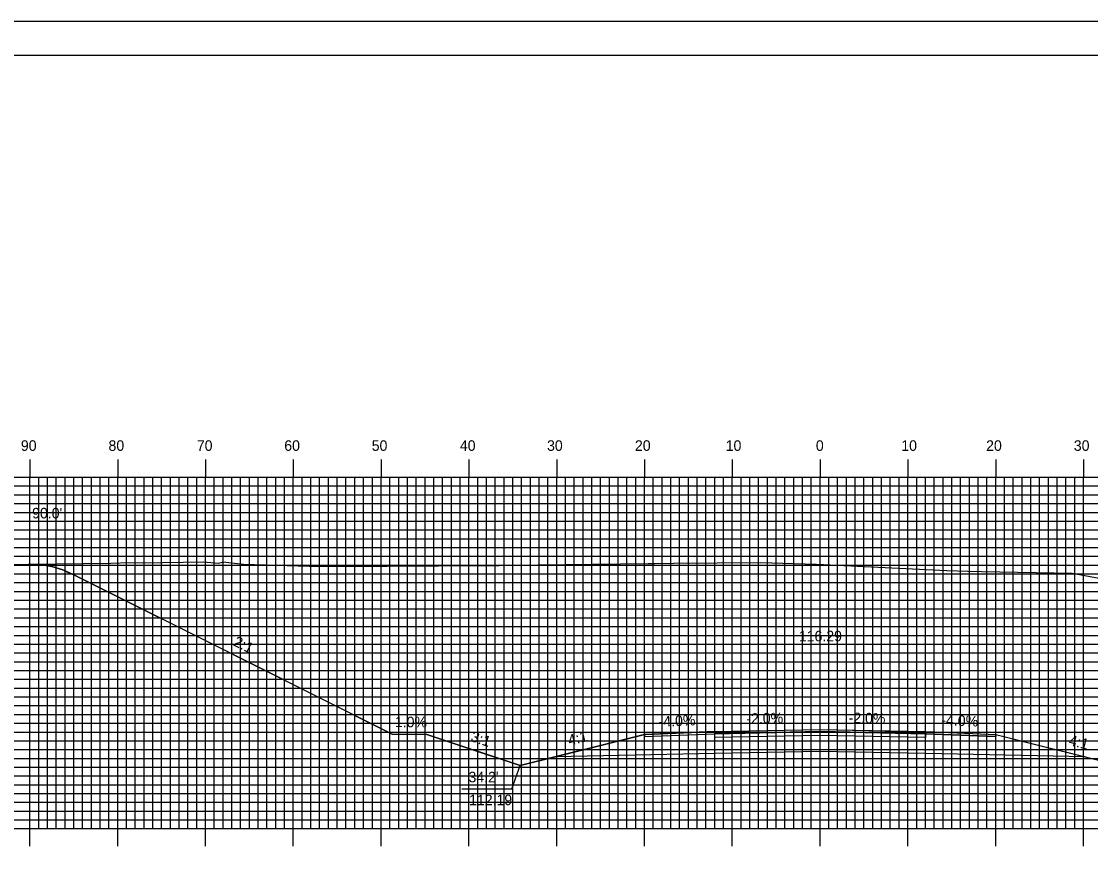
# Model space of a CAD drawing. Extents: x 1768087 to 1768430, y 442591 to 442811.
# Drawn here: x 1768162 to 1768283.8, y 442716.2 to 442810.5 of the extents above; entities that cross this region are included whole.
import ezdxf

# ---------------------------------------------------------------- set-up
doc = ezdxf.new("R2010")
doc.units = 0
for name, color, linetype in [('ANNOTATION', 7, 'Continuous'), ('BORDER', 7, 'Continuous'), ('D_Roadway_Centerline', 7, 'Continuous'), ('D_Roadway_Centerline_Text', 7, 'Continuous'), ('D_Roadway_Edge_Shoulder', 7, 'Continuous'), ('D_Roadway_Edge_TW', 7, 'Continuous'), ('D_Roadway_Pavement', 7, 'Continuous'), ('D_Roadway_SlopeLines', 7, 'Continuous'), ('D_Roadway_SubGrade', 7, 'Continuous'), ('D_Text_Standard', 7, 'Continuous'), ('H_V ANNOTATION', 7, 'Continuous'), ('MAJOR', 7, 'Continuous'), ('MINOR', 7, 'Continuous'), ('PLOT BOUNDARY', 7, 'Continuous'), ('S_Roadway_Centerline', 7, 'Continuous')]:
    doc.layers.add(name, color=color, linetype=linetype)

msp = doc.modelspace()

# ---------------------------------------------------------------- linework, layer by layer
at = {"layer": 'ANNOTATION'}
msp.add_lwpolyline([(1768212.17, 442723.21), (1768217.86, 442723.21), (1768218.79, 442725.85)], dxfattribs=at)
at = {"layer": 'BORDER'}
msp.add_lwpolyline([(1768103.36, 442596.67), (1768423.36, 442596.67), (1768423.36, 442806.67), (1768103.36, 442806.67)], close=True, dxfattribs=at)
at = {"layer": 'D_Roadway_Centerline'}
msp.add_lwpolyline([(1768162.96, 442748.79), (1768163.48, 442748.76), (1768164.21, 442748.72), (1768164.59, 442748.65), (1768165.46, 442748.5), (1768166.71, 442748.11), (1768167.18, 442747.91), (1768167.96, 442747.57), (1768187.51, 442737.79), (1768204.22, 442729.44), (1768208.16, 442729.4), (1768213.05, 442727.77), (1768218.79, 442725.85), (1768218.79, 442725.85), (1768218.79, 442725.85), (1768222.79, 442726.85), (1768232.96, 442729.4), (1768232.96, 442729.4), (1768240.96, 442729.72), (1768240.96, 442729.72), (1768252.96, 442729.96), (1768252.96, 442729.96), (1768264.06, 442729.73), (1768264.96, 442729.72), (1768272.96, 442729.4), (1768276.27, 442728.57), (1768283.14, 442726.85), (1768287.14, 442725.85)], dxfattribs=at)
at = {"layer": 'D_Roadway_Edge_Shoulder'}
for points in [[(1768240.96, 442729.72), (1768232.96, 442729.4), (1768232.96, 442729.15), (1768240.96, 442729.47)], [(1768264.96, 442729.72), (1768272.96, 442729.4), (1768272.96, 442729.15), (1768264.96, 442729.47)]]:
    msp.add_lwpolyline(points, close=True, dxfattribs=at)
at = {"layer": 'D_Roadway_Edge_TW'}
msp.add_lwpolyline([(1768240.96, 442729.47), (1768240.96, 442729.72), (1768252.96, 442729.96), (1768264.96, 442729.72), (1768264.96, 442729.47), (1768252.96, 442729.71)], close=True, dxfattribs=at)
at = {"layer": 'D_Roadway_Pavement'}
msp.add_lwpolyline([(1768240.96, 442729.05), (1768240.96, 442729.47), (1768252.96, 442729.71), (1768264.96, 442729.47), (1768264.96, 442729.05), (1768252.96, 442729.29)], close=True, dxfattribs=at)
at = {"layer": 'D_Roadway_SlopeLines'}
for points in [[(1768208.16, 442729.4), (1768204.22, 442729.44), (1768167.96, 442747.57), (1768166.71, 442748.11), (1768165.46, 442748.5), (1768164.21, 442748.72), (1768162.96, 442748.79)], [(1768218.79, 442725.85), (1768208.16, 442729.4)], [(1768232.96, 442729.4), (1768218.79, 442725.85)], [(1768272.96, 442729.4), (1768287.14, 442725.85)]]:
    msp.add_lwpolyline(points, dxfattribs=at)
at = {"layer": 'D_Roadway_SubGrade'}
msp.add_lwpolyline([(1768240.96, 442727.22), (1768222.79, 442726.85), (1768232.96, 442729.4), (1768232.96, 442729.15), (1768240.96, 442729.47), (1768252.96, 442729.71), (1768264.96, 442729.47), (1768272.96, 442729.15), (1768272.96, 442729.4), (1768283.14, 442726.85), (1768264.96, 442727.22), (1768252.96, 442727.46)], close=True, dxfattribs=at)
at = {"layer": 'MAJOR'}
for p, q in [((1768162.96, 442760.67), (1768162.96, 442758.67)), ((1768172.96, 442760.67), (1768172.96, 442758.67)), ((1768182.96, 442760.67), (1768182.96, 442758.67)), ((1768192.96, 442760.67), (1768192.96, 442758.67)), ((1768202.96, 442760.67), (1768202.96, 442758.67)), ((1768212.96, 442760.67), (1768212.96, 442758.67)), ((1768222.96, 442760.67), (1768222.96, 442758.67)), ((1768232.96, 442760.67), (1768232.96, 442758.67)), ((1768242.96, 442760.67), (1768242.96, 442758.67)), ((1768252.96, 442760.67), (1768252.96, 442758.67)), ((1768262.96, 442760.67), (1768262.96, 442758.67)), ((1768272.96, 442760.67), (1768272.96, 442758.67)), ((1768282.96, 442760.67), (1768282.96, 442758.67)), ((1768112.96, 442758.67), (1768392.96, 442758.67)), ((1768112.96, 442758.67), (1768392.96, 442758.67)), ((1768162.96, 442718.67), (1768162.96, 442758.67)), ((1768172.96, 442718.67), (1768172.96, 442758.67)), ((1768182.96, 442718.67), (1768182.96, 442758.67)), ((1768192.96, 442718.67), (1768192.96, 442758.67)), ((1768202.96, 442718.67), (1768202.96, 442758.67)), ((1768212.96, 442718.67), (1768212.96, 442758.67)), ((1768222.96, 442718.67), (1768222.96, 442758.67)), ((1768232.96, 442718.67), (1768232.96, 442758.67)), ((1768242.96, 442718.67), (1768242.96, 442758.67)), ((1768252.96, 442718.67), (1768252.96, 442758.67)), ((1768262.96, 442718.67), (1768262.96, 442758.67)), ((1768272.96, 442718.67), (1768272.96, 442758.67)), ((1768282.96, 442718.67), (1768282.96, 442758.67)), ((1768112.96, 442753.67), (1768392.96, 442753.67)), ((1768112.96, 442748.67), (1768392.96, 442748.67)), ((1768112.96, 442743.67), (1768392.96, 442743.67)), ((1768112.96, 442738.67), (1768392.96, 442738.67)), ((1768112.96, 442733.67), (1768392.96, 442733.67)), ((1768112.96, 442728.67), (1768392.96, 442728.67)), ((1768112.96, 442723.67), (1768392.96, 442723.67)), ((1768112.96, 442718.67), (1768392.96, 442718.67)), ((1768112.96, 442718.67), (1768392.96, 442718.67)), ((1768162.96, 442716.66), (1768162.96, 442718.67)), ((1768172.96, 442716.66), (1768172.96, 442718.67)), ((1768182.96, 442716.66), (1768182.96, 442718.67)), ((1768192.96, 442716.66), (1768192.96, 442718.67)), ((1768202.96, 442716.66), (1768202.96, 442718.67)), ((1768212.96, 442716.66), (1768212.96, 442718.67)), ((1768222.96, 442716.66), (1768222.96, 442718.67)), ((1768232.96, 442716.66), (1768232.96, 442718.67)), ((1768242.96, 442716.66), (1768242.96, 442718.67)), ((1768252.96, 442716.66), (1768252.96, 442718.67)), ((1768262.96, 442716.66), (1768262.96, 442718.67)), ((1768272.96, 442716.66), (1768272.96, 442718.67)), ((1768282.96, 442716.66), (1768282.96, 442718.67))]:
    msp.add_line(p, q, dxfattribs=at)
at = {"layer": 'MINOR'}
for p, q in [((1768163.96, 442718.67), (1768163.96, 442758.67)), ((1768164.96, 442718.67), (1768164.96, 442758.67)), ((1768165.96, 442718.67), (1768165.96, 442758.67)), ((1768166.96, 442718.67), (1768166.96, 442758.67)), ((1768167.96, 442718.67), (1768167.96, 442758.67)), ((1768168.96, 442718.67), (1768168.96, 442758.67)), ((1768169.96, 442718.67), (1768169.96, 442758.67)), ((1768170.96, 442718.67), (1768170.96, 442758.67)), ((1768171.96, 442718.67), (1768171.96, 442758.67)), ((1768173.96, 442718.67), (1768173.96, 442758.67)), ((1768174.96, 442718.67), (1768174.96, 442758.67)), ((1768175.96, 442718.67), (1768175.96, 442758.67)), ((1768176.96, 442718.67), (1768176.96, 442758.67)), ((1768177.96, 442718.67), (1768177.96, 442758.67)), ((1768178.96, 442718.67), (1768178.96, 442758.67)), ((1768179.96, 442718.67), (1768179.96, 442758.67)), ((1768180.96, 442718.67), (1768180.96, 442758.67)), ((1768181.96, 442718.67), (1768181.96, 442758.67)), ((1768183.96, 442718.67), (1768183.96, 442758.67)), ((1768184.96, 442718.67), (1768184.96, 442758.67)), ((1768185.96, 442718.67), (1768185.96, 442758.67)), ((1768186.96, 442718.67), (1768186.96, 442758.67)), ((1768187.96, 442718.67), (1768187.96, 442758.67)), ((1768188.96, 442718.67), (1768188.96, 442758.67)), ((1768189.96, 442718.67), (1768189.96, 442758.67)), ((1768190.96, 442718.67), (1768190.96, 442758.67)), ((1768191.96, 442718.67), (1768191.96, 442758.67)), ((1768193.96, 442718.67), (1768193.96, 442758.67)), ((1768194.96, 442718.67), (1768194.96, 442758.67)), ((1768195.96, 442718.67), (1768195.96, 442758.67)), ((1768196.96, 442718.67), (1768196.96, 442758.67)), ((1768197.96, 442718.67), (1768197.96, 442758.67)), ((1768198.96, 442718.67), (1768198.96, 442758.67)), ((1768199.96, 442718.67), (1768199.96, 442758.67)), ((1768200.96, 442718.67), (1768200.96, 442758.67)), ((1768201.96, 442718.67), (1768201.96, 442758.67)), ((1768203.96, 442718.67), (1768203.96, 442758.67)), ((1768204.96, 442718.67), (1768204.96, 442758.67)), ((1768205.96, 442718.67), (1768205.96, 442758.67)), ((1768206.96, 442718.67), (1768206.96, 442758.67)), ((1768207.96, 442718.67), (1768207.96, 442758.67)), ((1768208.96, 442718.67), (1768208.96, 442758.67)), ((1768209.96, 442718.67), (1768209.96, 442758.67)), ((1768210.96, 442718.67), (1768210.96, 442758.67)), ((1768211.96, 442718.67), (1768211.96, 442758.67)), ((1768213.96, 442718.67), (1768213.96, 442758.67)), ((1768214.96, 442718.67), (1768214.96, 442758.67)), ((1768215.96, 442718.67), (1768215.96, 442758.67)), ((1768216.96, 442718.67), (1768216.96, 442758.67)), ((1768217.96, 442718.67), (1768217.96, 442758.67)), ((1768218.96, 442718.67), (1768218.96, 442758.67)), ((1768219.96, 442718.67), (1768219.96, 442758.67)), ((1768220.96, 442718.67), (1768220.96, 442758.67)), ((1768221.96, 442718.67), (1768221.96, 442758.67)), ((1768223.96, 442718.67), (1768223.96, 442758.67)), ((1768224.96, 442718.67), (1768224.96, 442758.67)), ((1768225.96, 442718.67), (1768225.96, 442758.67)), ((1768226.96, 442718.67), (1768226.96, 442758.67)), ((1768227.96, 442718.67), (1768227.96, 442758.67)), ((1768228.96, 442718.67), (1768228.96, 442758.67)), ((1768229.96, 442718.67), (1768229.96, 442758.67)), ((1768230.96, 442718.67), (1768230.96, 442758.67)), ((1768231.96, 442718.67), (1768231.96, 442758.67)), ((1768233.96, 442718.67), (1768233.96, 442758.67)), ((1768234.96, 442718.67), (1768234.96, 442758.67)), ((1768235.96, 442718.67), (1768235.96, 442758.67)), ((1768236.96, 442718.67), (1768236.96, 442758.67)), ((1768237.96, 442718.67), (1768237.96, 442758.67)), ((1768238.96, 442718.67), (1768238.96, 442758.67)), ((1768239.96, 442718.67), (1768239.96, 442758.67)), ((1768240.96, 442718.67), (1768240.96, 442758.67)), ((1768241.96, 442718.67), (1768241.96, 442758.67)), ((1768243.96, 442718.67), (1768243.96, 442758.67)), ((1768244.96, 442718.67), (1768244.96, 442758.67)), ((1768245.96, 442718.67), (1768245.96, 442758.67)), ((1768246.96, 442718.67), (1768246.96, 442758.67)), ((1768247.96, 442718.67), (1768247.96, 442758.67)), ((1768248.96, 442718.67), (1768248.96, 442758.67)), ((1768249.96, 442718.67), (1768249.96, 442758.67)), ((1768250.96, 442718.67), (1768250.96, 442758.67)), ((1768251.96, 442718.67), (1768251.96, 442758.67)), ((1768253.96, 442718.67), (1768253.96, 442758.67)), ((1768254.96, 442718.67), (1768254.96, 442758.67)), ((1768255.96, 442718.67), (1768255.96, 442758.67)), ((1768256.96, 442718.67), (1768256.96, 442758.67)), ((1768257.96, 442718.67), (1768257.96, 442758.67)), ((1768258.96, 442718.67), (1768258.96, 442758.67)), ((1768259.96, 442718.67), (1768259.96, 442758.67)), ((1768260.96, 442718.67), (1768260.96, 442758.67)), ((1768261.96, 442718.67), (1768261.96, 442758.67)), ((1768263.96, 442718.67), (1768263.96, 442758.67)), ((1768264.96, 442718.67), (1768264.96, 442758.67)), ((1768265.96, 442718.67), (1768265.96, 442758.67)), ((1768266.96, 442718.67), (1768266.96, 442758.67)), ((1768267.96, 442718.67), (1768267.96, 442758.67)), ((1768268.96, 442718.67), (1768268.96, 442758.67)), ((1768269.96, 442718.67), (1768269.96, 442758.67)), ((1768270.96, 442718.67), (1768270.96, 442758.67)), ((1768271.96, 442718.67), (1768271.96, 442758.67)), ((1768273.96, 442718.67), (1768273.96, 442758.67)), ((1768274.96, 442718.67), (1768274.96, 442758.67)), ((1768275.96, 442718.67), (1768275.96, 442758.67)), ((1768276.96, 442718.67), (1768276.96, 442758.67)), ((1768277.96, 442718.67), (1768277.96, 442758.67)), ((1768278.96, 442718.67), (1768278.96, 442758.67)), ((1768279.96, 442718.67), (1768279.96, 442758.67)), ((1768280.96, 442718.67), (1768280.96, 442758.67)), ((1768281.96, 442718.67), (1768281.96, 442758.67)), ((1768112.96, 442757.67), (1768392.96, 442757.67)), ((1768112.96, 442756.67), (1768392.96, 442756.67)), ((1768112.96, 442755.67), (1768392.96, 442755.67)), ((1768112.96, 442754.67), (1768392.96, 442754.67)), ((1768112.96, 442752.67), (1768392.96, 442752.67)), ((1768112.96, 442751.67), (1768392.96, 442751.67)), ((1768112.96, 442750.67), (1768392.96, 442750.67)), ((1768112.96, 442749.67), (1768392.96, 442749.67)), ((1768112.96, 442747.67), (1768392.96, 442747.67)), ((1768112.96, 442746.67), (1768392.96, 442746.67)), ((1768112.96, 442745.67), (1768392.96, 442745.67)), ((1768112.96, 442744.67), (1768392.96, 442744.67)), ((1768112.96, 442742.67), (1768392.96, 442742.67)), ((1768112.96, 442741.67), (1768392.96, 442741.67)), ((1768112.96, 442740.67), (1768392.96, 442740.67)), ((1768112.96, 442739.67), (1768392.96, 442739.67)), ((1768112.96, 442737.67), (1768392.96, 442737.67)), ((1768112.96, 442736.67), (1768392.96, 442736.67)), ((1768112.96, 442735.67), (1768392.96, 442735.67)), ((1768112.96, 442734.67), (1768392.96, 442734.67)), ((1768112.96, 442732.67), (1768392.96, 442732.67)), ((1768112.96, 442731.67), (1768392.96, 442731.67)), ((1768112.96, 442730.67), (1768392.96, 442730.67)), ((1768112.96, 442729.67), (1768392.96, 442729.67)), ((1768112.96, 442727.67), (1768392.96, 442727.67)), ((1768112.96, 442726.67), (1768392.96, 442726.67)), ((1768112.96, 442725.67), (1768392.96, 442725.67)), ((1768112.96, 442724.67), (1768392.96, 442724.67)), ((1768112.96, 442722.67), (1768392.96, 442722.67)), ((1768112.96, 442721.67), (1768392.96, 442721.67)), ((1768112.96, 442720.67), (1768392.96, 442720.67)), ((1768112.96, 442719.67), (1768392.96, 442719.67))]:
    msp.add_line(p, q, dxfattribs=at)
at = {"layer": 'PLOT BOUNDARY'}
msp.add_lwpolyline([(1768087.18, 442590.55), (1768427.18, 442590.55), (1768427.18, 442810.55), (1768087.18, 442810.55)], close=True, dxfattribs=at)
at = {"layer": 'S_Roadway_Centerline'}
msp.add_lwpolyline([(1768156.3, 442748.69), (1768162.76, 442748.78), (1768172.19, 442748.89), (1768174.33, 442748.96), (1768175.78, 442748.94), (1768182.74, 442749.02), (1768184.44, 442748.9), (1768184.91, 442749.01), (1768184.95, 442749.04), (1768187.28, 442748.79), (1768194.77, 442748.55), (1768197.96, 442748.51), (1768203.6, 442748.55), (1768215.37, 442748.62), (1768216.41, 442748.63), (1768216.44, 442748.64), (1768216.76, 442748.64), (1768217.66, 442748.64), (1768233.36, 442748.85), (1768234.15, 442748.85), (1768236.3, 442748.88), (1768246.18, 442748.95), (1768252.55, 442748.78), (1768267.41, 442748.06), (1768269.79, 442747.97), (1768271.37, 442747.92), (1768281.68, 442747.76), (1768290.88, 442746.03)], dxfattribs=at)

# ---------------------------------------------------------------- texts
at = {"layer": 'ANNOTATION'}
for s, rotation, p in [('2:1', 333.4342, (1768186.03, 442739.57)), ('1.0%', 359.4324, (1768204.52, 442730.23)), ('-4.0%', 2.2905, (1768234.59, 442730.26)), ('-2.0%', 1.1458, (1768244.57, 442730.59)), ('-2.0%', 358.8542, (1768256.2, 442730.69)), ('-4.0%', 357.7095, (1768266.75, 442730.45)), ('3:1', 341.5631, (1768213.08, 442728.66)), ('4:1', 14.0389, (1768224.41, 442728.12)), ('4:1', 345.9625, (1768281.21, 442728.2))]:
    msp.add_text(s, height=1.2, rotation=rotation, dxfattribs=at).set_placement(p)
for s, p in [("34.2'", (1768212.91, 442723.94)), ('112.19', (1768212.98, 442721.34))]:
    msp.add_text(s, height=1.2, dxfattribs=at).set_placement(p)
at = {"layer": 'D_Roadway_Centerline'}
for s, p in [('C', (1768252.96, 442729.96)), ('L', (1768252.96, 442729.95))]:
    msp.add_text(s, height=0.0146, dxfattribs=at).set_placement(p)
at = {"layer": 'D_Roadway_Centerline_Text'}
msp.add_text('116.29', height=1.2, dxfattribs=at).set_placement((1768250.54, 442739.99))
at = {"layer": 'D_Text_Standard'}
msp.add_text("90.0'", height=1.2, dxfattribs=at).set_placement((1768163.21, 442753.98))
at = {"layer": 'H_V ANNOTATION'}
for s, p in [('90', (1768161.93, 442761.67)), ('80', (1768171.91, 442761.67)), ('70', (1768181.97, 442761.67)), ('60', (1768191.93, 442761.67)), ('50', (1768201.89, 442761.67)), ('40', (1768211.93, 442761.67)), ('30', (1768221.86, 442761.67)), ('20', (1768231.87, 442761.67)), ('10', (1768242.21, 442761.67)), ('0', (1768252.48, 442761.67)), ('10', (1768262.21, 442761.67)), ('20', (1768271.87, 442761.67)), ('30', (1768281.86, 442761.67))]:
    msp.add_text(s, height=1.2, dxfattribs=at).set_placement(p)

doc.saveas('drawing.dxf')
